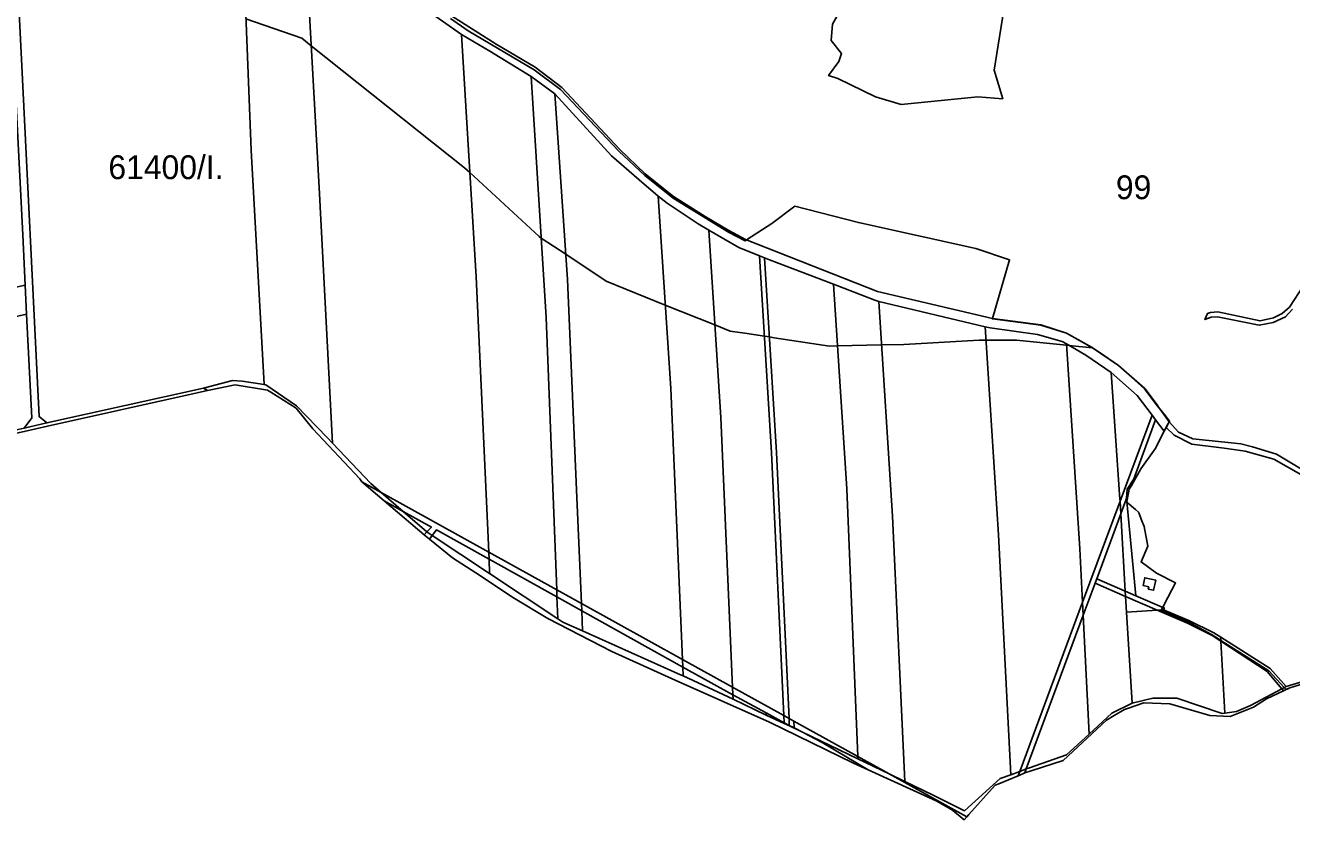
# Model space of a CAD drawing. Extents: x -522079 to -518792, y -1142400 to -1139961.
# Drawn here: x -520002 to -519205, y -1141872 to -1141371 of the extents above; entities that cross this region are included whole.
import ezdxf

# ---------------------------------------------------------------- set-up
doc = ezdxf.new("R2010")
doc.units = 0
for name, color, linetype in [('Hranice parcel', 7, 'Continuous'), ('Parcelní čísla', 7, 'Continuous'), ('Poz předměty', 7, 'Continuous'), ('Značky bodu BP', 7, 'Continuous'), ('Značky budov', 7, 'Continuous')]:
    doc.layers.add(name, color=color, linetype=linetype)

msp = doc.modelspace()

# ---------------------------------------------------------------- linework, layer by layer
at = {"layer": 'Hranice parcel'}
for points in [[(-519998.35, -1141618.37), (-520001.59, -1141552.99), (-520002.49, -1141534.74), (-520004.05, -1141503.1), (-520007.71, -1141429.14), (-520010.91, -1141364.55), (-520011.78, -1141349.43), (-520013.01, -1141327.96), (-520014.41, -1141303.65), (-520015.8, -1141279.3), (-520015.63, -1141269.2), (-520020.82, -1141261.97), (-520005.98, -1141266.96), (-520010.89, -1141271.2), (-520005.29, -1141383.92), (-519993.67, -1141617.6), (-519988.83, -1141621.62), (-520003.08, -1141624.98)], [(-520266.52, -1141683.24), (-520133.69, -1141653.91), (-520003.08, -1141624.98), (-519988.83, -1141621.62), (-519890.16, -1141599.67), (-519887.54, -1141601.15), (-519894.12, -1141602.61), (-519988.36, -1141623.57), (-520003.05, -1141627.05), (-520133.25, -1141655.87), (-520266.08, -1141685.14)], [(-519292.71, -1141616.64), (-519290.49, -1141619.61), (-519305.95, -1141661.39), (-519307.13, -1141663.43), (-519307.53, -1141665.67), (-519312.39, -1141678.8), (-519312.84, -1141670.86)], [(-519215.97, -1141644.42), (-519234.03, -1141639.34), (-519247.24, -1141637.55), (-519267.72, -1141635.03), (-519278.79, -1141629.39), (-519283.88, -1141624.46), (-519281.83, -1141620.82), (-519276.07, -1141627.44), (-519266.93, -1141631.65), (-519236.73, -1141634.83), (-519229.49, -1141636.68), (-519214.22, -1141641.4), (-519195.4, -1141652.58), (-519185.55, -1141666.07), (-519168.83, -1141692.07), (-519157.76, -1141703.36), (-519119.77, -1141724.36), (-519107.07, -1141732.42), (-519111.34, -1141734.71), (-519122.24, -1141726.88), (-519160.32, -1141706.01), (-519170.28, -1141695.6), (-519197.57, -1141654.98)], [(-519790.37, -1141658.77), (-519778.21, -1141665.51), (-519764.48, -1141677.36), (-519776.39, -1141670.73)], [(-519778.21, -1141665.51), (-519710.49, -1141703.04), (-519710.31, -1141707.49), (-519743.43, -1141689.07), (-519746.19, -1141692.62), (-519748.73, -1141690.94), (-519749.42, -1141690.34), (-519746.63, -1141687.29), (-519764.48, -1141677.36)], [(-519312.39, -1141678.8), (-519327.57, -1141719.82), (-519328.61, -1141722.63), (-519336.07, -1141742.78), (-519336.47, -1141734.52), (-519312.84, -1141670.86)], [(-519746.19, -1141692.62), (-519747.91, -1141694.83), (-519751.14, -1141692.22), (-519749.42, -1141690.34), (-519748.73, -1141690.94)], [(-519710.49, -1141703.04), (-519667.71, -1141726.74), (-519667.54, -1141731.28), (-519710.31, -1141707.49)], [(-519309.44, -1141730.94), (-519328.61, -1141722.63), (-519327.57, -1141719.82), (-519309.63, -1141727.6)], [(-519298.29, -1141724.1), (-519297.27, -1141719.22), (-519290.41, -1141720.65), (-519291.74, -1141727), (-519295.11, -1141726.32), (-519294.81, -1141724.84)], [(-519667.54, -1141731.28), (-519667.71, -1141726.74), (-519652.11, -1141735.39), (-519651.91, -1141739.97)], [(-519285.49, -1141739.31), (-519289.52, -1141739.58), (-519309.44, -1141730.94), (-519309.63, -1141727.6), (-519302.86, -1141730.53), (-519284.96, -1141738.29)], [(-519588.39, -1141770.7), (-519588.18, -1141775.42), (-519651.91, -1141739.97), (-519652.11, -1141735.39)], [(-519336.47, -1141734.52), (-519336.07, -1141742.78), (-519371.92, -1141839.65), (-519376.07, -1141841.19)], [(-519192.31, -1141784.44), (-519205.85, -1141788.49), (-519209.88, -1141790.38), (-519211, -1141789.08), (-519208.31, -1141787.64), (-519193.63, -1141783.33), (-519181.21, -1141780.54), (-519173.18, -1141777.23), (-519164.17, -1141772.59), (-519130.56, -1141747.22), (-519111.34, -1141734.71), (-519107.07, -1141732.42), (-519106.29, -1141740.33), (-519117.64, -1141741.85), (-519132.98, -1141750.7), (-519141.38, -1141757.45), (-519162.82, -1141773.79), (-519171.52, -1141778.29), (-519182.83, -1141782.69)], [(-519253.85, -1141753.9), (-519249.47, -1141756.69), (-519249.34, -1141759.14), (-519254.9, -1141755.61), (-519270.39, -1141747.88), (-519289.52, -1141739.58), (-519285.49, -1141739.31), (-519269.54, -1141746.07)], [(-519249.47, -1141756.69), (-519218.36, -1141776.45), (-519208.31, -1141787.64), (-519211, -1141789.08), (-519220.27, -1141778.33), (-519249.34, -1141759.14)], [(-519556.77, -1141792.9), (-519588.18, -1141775.42), (-519588.39, -1141770.7), (-519556.98, -1141788.11)], [(-519556.77, -1141792.9), (-519556.98, -1141788.11), (-519524.56, -1141806.07), (-519524.35, -1141810.51), (-519535.73, -1141804.33)], [(-519524.35, -1141810.51), (-519524.56, -1141806.07), (-519521.37, -1141807.84), (-519521.17, -1141812.18)], [(-519521.17, -1141812.18), (-519521.37, -1141807.84), (-519518.28, -1141809.56), (-519518.08, -1141813.8)], [(-519477.97, -1141833.34), (-519512.87, -1141816.53), (-519518.08, -1141813.8), (-519518.28, -1141809.56), (-519478.03, -1141831.87)], [(-519477.97, -1141833.34), (-519458.26, -1141842.83), (-519409.46, -1141869.87), (-519411.05, -1141871.62), (-519418.41, -1141865.69), (-519428.71, -1141859.77), (-519471.59, -1141840.28), (-519500.53, -1141823.01), (-519512.87, -1141816.53)], [(-519478.03, -1141831.87), (-519458.26, -1141842.83), (-519477.97, -1141833.34)], [(-519377.1, -1141843.96), (-519376.07, -1141841.19), (-519371.92, -1141839.65), (-519372.86, -1141842.19), (-519376.08, -1141843.54)]]:
    msp.add_lwpolyline(points, close=True, dxfattribs=at)
for points in [[(-519733.94, -1141365.09), (-519705.92, -1141383), (-519681.23, -1141397.53), (-519664.49, -1141410.15), (-519628.16, -1141449.15), (-519611.87, -1141464.55), (-519594.12, -1141478.91), (-519574.1, -1141491.51), (-519559.27, -1141500.34), (-519548.85, -1141506.03), (-519465.6, -1141538.79), (-519393.2, -1141555.81), (-519362.75, -1141559.82), (-519346.5, -1141565.05), (-519330.14, -1141574.2), (-519313.9, -1141585.4), (-519297.36, -1141600.15), (-519289.76, -1141610.43), (-519286.19, -1141615.06), (-519281.83, -1141620.82), (-519283.88, -1141624.46), (-519285.15, -1141626.73), (-519290.49, -1141619.61), (-519292.71, -1141616.64), (-519301.98, -1141604.24), (-519318.43, -1141589.84), (-519334.38, -1141578.92), (-519346.66, -1141571.83), (-519349.35, -1141570.28), (-519364.95, -1141565.79), (-519394.67, -1141561.74), (-519397.82, -1141561.07), (-519464.89, -1141545.09), (-519467.42, -1141544.19), (-519493.41, -1141534.2), (-519533.7, -1141518.85), (-519536.79, -1141517.61), (-519539.97, -1141516.35), (-519553.06, -1141511.15), (-519571.87, -1141500.11), (-519578.53, -1141496.09), (-519598.08, -1141483.22), (-519603.81, -1141478.65), (-519615.77, -1141468.45), (-519633.24, -1141453.23), (-519668.96, -1141414.21), (-519683.78, -1141403.39), (-519709.78, -1141387.41), (-519727.64, -1141376.95), (-519751.63, -1141360.04)], [(-519204.3, -1141549.93), (-519208.65, -1141554.69), (-519216.52, -1141558.38), (-519225.22, -1141560.03), (-519251.39, -1141554.86), (-519255.57, -1141555.02), (-519259.41, -1141556.52), (-519257.81, -1141552.73), (-519255.9, -1141551.98), (-519251.3, -1141551.66), (-519224.64, -1141557.32), (-519216.28, -1141555.43), (-519210.78, -1141552.72), (-519206.19, -1141548.7), (-519197.16, -1141534.83)]]:
    msp.add_lwpolyline(points, dxfattribs=at)
at = {"layer": 'Parcelní čísla'}
for points in [[(-519988.83, -1141621.62), (-519993.67, -1141617.6), (-520005.29, -1141383.92), (-520010.89, -1141271.2), (-520005.98, -1141266.96), (-519865.42, -1141315.8), (-519860.18, -1141449.65), (-519851.95, -1141597.5), (-519865.85, -1141595.23), (-519871.86, -1141594.87), (-519890.16, -1141599.67)], [(-519865.42, -1141315.8), (-519825.24, -1141330.38), (-519817.29, -1141473.31), (-519808.88, -1141634.44), (-519812.26, -1141630.88), (-519831.57, -1141610.83), (-519850.96, -1141597.66), (-519851.95, -1141597.5), (-519860.18, -1141449.65)], [(-519825.24, -1141330.38), (-519793.08, -1141341.43), (-519751.63, -1141360.04), (-519727.64, -1141376.95), (-519718.52, -1141529.55), (-519710.49, -1141703.04), (-519778.21, -1141665.51), (-519784.86, -1141659.77), (-519808.88, -1141634.44), (-519817.29, -1141473.31)], [(-519710.49, -1141703.04), (-519718.52, -1141529.55), (-519727.64, -1141376.95), (-519709.78, -1141387.41), (-519683.78, -1141403.39), (-519674.25, -1141555.28), (-519667.71, -1141726.74)], [(-519683.78, -1141403.39), (-519668.96, -1141414.21), (-519660.95, -1141531.22), (-519655.21, -1141663.8), (-519652.11, -1141735.39), (-519667.71, -1141726.74), (-519674.25, -1141555.28)], [(-519660.95, -1141531.22), (-519668.96, -1141414.21), (-519633.24, -1141453.23), (-519615.77, -1141468.45), (-519603.81, -1141478.65), (-519595.83, -1141599.95), (-519588.39, -1141770.7), (-519652.11, -1141735.39), (-519655.21, -1141663.8)], [(-519564.39, -1141618.27), (-519556.98, -1141788.11), (-519588.39, -1141770.7), (-519595.83, -1141599.95), (-519603.81, -1141478.65), (-519598.08, -1141483.22), (-519578.53, -1141496.09), (-519571.87, -1141500.11)], [(-519564.39, -1141618.27), (-519571.87, -1141500.11), (-519553.06, -1141511.15), (-519539.97, -1141516.35), (-519532.32, -1141640.4), (-519524.56, -1141806.07), (-519556.98, -1141788.11)], [(-519539.97, -1141516.35), (-519536.79, -1141517.61), (-519529.23, -1141640.2), (-519521.37, -1141807.84), (-519524.56, -1141806.07), (-519532.32, -1141640.4)], [(-519518.28, -1141809.56), (-519521.37, -1141807.84), (-519529.23, -1141640.2), (-519536.79, -1141517.61), (-519533.7, -1141518.85), (-519493.41, -1141534.2), (-519484.95, -1141663.16), (-519478.03, -1141831.87)], [(-520141.93, -1141565.64), (-520002.49, -1141534.74), (-520001.59, -1141552.99), (-520274.84, -1141614.95), (-520276.82, -1141595.78)], [(-519464.89, -1141545.09), (-519456.22, -1141680.46), (-519448.38, -1141847.58), (-519458.26, -1141842.83), (-519478.03, -1141831.87), (-519484.95, -1141663.16), (-519493.41, -1141534.2), (-519467.42, -1141544.19)], [(-519381.7, -1141843.28), (-519388.28, -1141845.72), (-519410.94, -1141866.01), (-519430.66, -1141856.11), (-519448.38, -1141847.58), (-519456.22, -1141680.46), (-519464.89, -1141545.09), (-519397.82, -1141561.07), (-519389.39, -1141692.08)], [(-520001.59, -1141552.99), (-519998.35, -1141618.37), (-520003.08, -1141624.98), (-520133.69, -1141653.91), (-520266.52, -1141683.24), (-520268.73, -1141674.23), (-520274.84, -1141614.95)], [(-519338.11, -1141700.9), (-519336.47, -1141734.52), (-519376.07, -1141841.19), (-519381.7, -1141843.28), (-519389.39, -1141692.08), (-519397.82, -1141561.07), (-519394.67, -1141561.74), (-519364.95, -1141565.79), (-519349.35, -1141570.28), (-519346.66, -1141571.83)], [(-519312.91, -1141669.62), (-519312.84, -1141670.86), (-519336.47, -1141734.52), (-519338.11, -1141700.9), (-519346.66, -1141571.83), (-519334.38, -1141578.92), (-519318.43, -1141589.84)], [(-519318.43, -1141589.84), (-519301.98, -1141604.24), (-519292.71, -1141616.64), (-519312.84, -1141670.86), (-519312.91, -1141669.62)], [(-519871.86, -1141594.87), (-519865.85, -1141595.23), (-519851.95, -1141597.5), (-519850.96, -1141597.66), (-519831.57, -1141610.83), (-519812.26, -1141630.88), (-519808.88, -1141634.44), (-519784.86, -1141659.77), (-519778.21, -1141665.51), (-519790.37, -1141658.77), (-519791.74, -1141656.89), (-519821.3, -1141625.26), (-519831.88, -1141612.23), (-519847.75, -1141602.33), (-519849.83, -1141601.06), (-519870.13, -1141597.7), (-519887.54, -1141601.15), (-519890.16, -1141599.67)], [(-519776.39, -1141670.73), (-519764.48, -1141677.36), (-519749.42, -1141690.34), (-519751.14, -1141692.22)], [(-519764.48, -1141677.36), (-519746.63, -1141687.29), (-519749.42, -1141690.34)], [(-519710.31, -1141707.49), (-519709.93, -1141716.59), (-519746.19, -1141692.62), (-519743.43, -1141689.07)], [(-519718.63, -1141715.98), (-519733.23, -1141706.57), (-519747.91, -1141694.83), (-519746.19, -1141692.62), (-519709.93, -1141716.59), (-519667.02, -1141744.96), (-519663.82, -1141747.08), (-519651.37, -1141752.53), (-519589.8, -1141780.27), (-519588.09, -1141781.01), (-519556.64, -1141795.77), (-519535.66, -1141805.67), (-519524.32, -1141811.02), (-519521.15, -1141812.55), (-519512.87, -1141816.53), (-519500.53, -1141823.01), (-519471.59, -1141840.28), (-519480.84, -1141836.08), (-519533.59, -1141810.27), (-519593.13, -1141783.65), (-519633.06, -1141765.56), (-519673.22, -1141744.78), (-519694.8, -1141731.79)], [(-519667.54, -1141731.28), (-519667.02, -1141744.96), (-519709.93, -1141716.59), (-519710.31, -1141707.49)], [(-519305.24, -1141798.22), (-519318.06, -1141804.43), (-519332.42, -1141817.72), (-519336.07, -1141742.78), (-519328.61, -1141722.63), (-519309.44, -1141730.94), (-519308.88, -1141740.9)], [(-519667.54, -1141731.28), (-519651.91, -1141739.97), (-519651.37, -1141752.53), (-519663.82, -1141747.08), (-519667.02, -1141744.96)], [(-519289.52, -1141739.58), (-519308.88, -1141740.9), (-519309.44, -1141730.94)], [(-519588.18, -1141775.42), (-519588.09, -1141781.01), (-519589.8, -1141780.27), (-519651.37, -1141752.53), (-519651.91, -1141739.97)], [(-519336.07, -1141742.78), (-519332.42, -1141817.72), (-519346.6, -1141830.84), (-519369.96, -1141838.92), (-519371.92, -1141839.65)], [(-519254.9, -1141755.61), (-519249.34, -1141759.14), (-519246.92, -1141804.45), (-519248.63, -1141804.68), (-519277.03, -1141795.09), (-519292.12, -1141794.98), (-519305.24, -1141798.22), (-519308.88, -1141740.9), (-519289.52, -1141739.58), (-519270.39, -1141747.88)], [(-519220.27, -1141778.33), (-519211, -1141789.08), (-519230.77, -1141799.67), (-519239.54, -1141803.44), (-519246.92, -1141804.45), (-519249.34, -1141759.14)], [(-519556.64, -1141795.77), (-519588.09, -1141781.01), (-519588.18, -1141775.42), (-519556.77, -1141792.9)], [(-519556.64, -1141795.77), (-519556.77, -1141792.9), (-519535.73, -1141804.33), (-519535.66, -1141805.67)], [(-519243.51, -1141806.68), (-519256.37, -1141806.05), (-519281.47, -1141798.57), (-519297.93, -1141798.04), (-519308.25, -1141801.56), (-519310.14, -1141802.21), (-519316.53, -1141805.97), (-519321.4, -1141808.82), (-519348.63, -1141834.32), (-519368.78, -1141840.86), (-519372.86, -1141842.19), (-519371.92, -1141839.65), (-519369.96, -1141838.92), (-519346.6, -1141830.84), (-519332.42, -1141817.72), (-519318.06, -1141804.43), (-519305.24, -1141798.22), (-519292.12, -1141794.98), (-519277.03, -1141795.09), (-519248.63, -1141804.68), (-519246.92, -1141804.45), (-519239.54, -1141803.44), (-519230.77, -1141799.67), (-519211, -1141789.08), (-519209.88, -1141790.38), (-519220.64, -1141795.43), (-519228.74, -1141800.67)], [(-519535.73, -1141804.33), (-519524.35, -1141810.51), (-519524.32, -1141811.02), (-519535.66, -1141805.67)], [(-519521.15, -1141812.55), (-519524.32, -1141811.02), (-519524.35, -1141810.51), (-519521.17, -1141812.18)], [(-519512.87, -1141816.53), (-519521.15, -1141812.55), (-519521.17, -1141812.18), (-519518.08, -1141813.8)], [(-519389.29, -1141849.01), (-519391.5, -1141849.93), (-519408.1, -1141868.36), (-519409.46, -1141869.87), (-519458.26, -1141842.83), (-519448.38, -1141847.58), (-519430.66, -1141856.11), (-519410.94, -1141866.01), (-519388.28, -1141845.72), (-519381.7, -1141843.28), (-519376.07, -1141841.19), (-519377.1, -1141843.96)]]:
    msp.add_lwpolyline(points, close=True, dxfattribs=at)
at = {"layer": 'Poz předměty'}
for points in [[(-519290.49, -1141619.61), (-519285.15, -1141626.73), (-519290.81, -1141638.01), (-519299.72, -1141650.6), (-519305.95, -1141661.39)], [(-519308.5, -1141671.02), (-519302.86, -1141730.53), (-519309.63, -1141727.6), (-519312.39, -1141678.8), (-519307.53, -1141665.67)], [(-519309.63, -1141727.6), (-519327.57, -1141719.82), (-519312.39, -1141678.8)]]:
    msp.add_lwpolyline(points, close=True, dxfattribs=at)
at = {"layer": 'Značky bodu BP'}
for points in [[(-519863.42, -1141366.88), (-519828.32, -1141379.25), (-519822.25, -1141384.07), (-519725.68, -1141460.78), (-519722.45, -1141463.77), (-519678.79, -1141504.16), (-519677.4, -1141505.09), (-519662.03, -1141515.37), (-519636.59, -1141532.38), (-519599.29, -1141547.35), (-519568.09, -1141559.87), (-519558.44, -1141563.74), (-519556.95, -1141563.96), (-519549.16, -1141565.14), (-519536.85, -1141566.99), (-519536.62, -1141567.02), (-519533.71, -1141567.46), (-519530.67, -1141567.92), (-519495.92, -1141573.15), (-519490.86, -1141573.03), (-519463.14, -1141572.42), (-519449.03, -1141572.1), (-519401.62, -1141569.49), (-519397.28, -1141569.49), (-519378.18, -1141569.49), (-519346.61, -1141572.59), (-519345.08, -1141572.74), (-519330.18, -1141574.2), (-519325.31, -1141577.53), (-519313.9, -1141585.33), (-519297.31, -1141600.01), (-519289.56, -1141610.31), (-519288.55, -1141611.63), (-519286.09, -1141614.85), (-519285.08, -1141616.18), (-519281.71, -1141620.6), (-519281.83, -1141620.82), (-519283.73, -1141624.25), (-519283.86, -1141624.48), (-519285, -1141626.52), (-519286.13, -1141628.69), (-519290.81, -1141638.01), (-519299.72, -1141650.6), (-519305.95, -1141661.39), (-519304.41, -1141657.24), (-519308.29, -1141663.27), (-519308.84, -1141669.03), (-519308.86, -1141669.27), (-519307.53, -1141665.67), (-519308.5, -1141671.02), (-519308.44, -1141671.65), (-519303.06, -1141676.16), (-519301.18, -1141677.74), (-519300.85, -1141678.61), (-519299.51, -1141682.18), (-519297.77, -1141686.8), (-519295.29, -1141699.2), (-519299.57, -1141709.24), (-519289.85, -1141716.31), (-519277.9, -1141722.39), (-519285.04, -1141736), (-519286.01, -1141737.83), (-519286.11, -1141738.02), (-519286.86, -1141739.4), (-519287.01, -1141739.67), (-519270.39, -1141746.69), (-519255.22, -1141754.92), (-519250.82, -1141757.69), (-519249.37, -1141758.61), (-519219.1, -1141777.78), (-519209.49, -1141788.27), (-519208.58, -1141789.26), (-519208.35, -1141789.66), (-519209.88, -1141790.38), (-519220.64, -1141795.43), (-519228.74, -1141800.67), (-519243.51, -1141806.68), (-519256.37, -1141806.05), (-519281.47, -1141798.57), (-519297.93, -1141798.04), (-519308.25, -1141801.56), (-519310.14, -1141802.21), (-519316.53, -1141805.97), (-519321.4, -1141808.82), (-519348.63, -1141834.32), (-519368.78, -1141840.86), (-519372.86, -1141842.19), (-519376.08, -1141843.54), (-519377.1, -1141843.96), (-519389.29, -1141849.01), (-519391.5, -1141849.93), (-519408.1, -1141868.36), (-519409.46, -1141869.87), (-519411.05, -1141871.62), (-519418.41, -1141865.69), (-519428.71, -1141859.77), (-519471.59, -1141840.28), (-519480.84, -1141836.08), (-519533.59, -1141810.27), (-519593.13, -1141783.65), (-519633.06, -1141765.56), (-519673.22, -1141744.78), (-519694.8, -1141731.79), (-519718.63, -1141715.98), (-519733.23, -1141706.57), (-519747.91, -1141694.83), (-519751.14, -1141692.22), (-519776.39, -1141670.73), (-519790.37, -1141658.77), (-519791.74, -1141656.89), (-519821.3, -1141625.26), (-519831.88, -1141612.23), (-519847.75, -1141602.33), (-519849.83, -1141601.06), (-519870.13, -1141597.7), (-519887.54, -1141601.15), (-519894.12, -1141602.61), (-519988.36, -1141623.57), (-520003.05, -1141627.05)], [(-519734.68, -1141366.82), (-519723.37, -1141374.45), (-519681.85, -1141399.04), (-519665.4, -1141411.5), (-519628.6, -1141450.42), (-519612.25, -1141465.74), (-519594.44, -1141480.03), (-519559.52, -1141501.31), (-519549.08, -1141506.95), (-519548.11, -1141506.32), (-519532.23, -1141495.98), (-519517.64, -1141485.04), (-519477.67, -1141495.35), (-519403.69, -1141511.76), (-519382.45, -1141518.76), (-519393.21, -1141555.81), (-519393.29, -1141556.08), (-519362.83, -1141559.96), (-519346.58, -1141565.12), (-519330.41, -1141574.07), (-519330.18, -1141574.2), (-519345.08, -1141572.74), (-519346.61, -1141572.59), (-519378.18, -1141569.49), (-519397.28, -1141569.49), (-519401.62, -1141569.49), (-519449.03, -1141572.1), (-519463.14, -1141572.42), (-519490.86, -1141573.03), (-519495.92, -1141573.15), (-519530.67, -1141567.92), (-519533.71, -1141567.46), (-519536.62, -1141567.02), (-519536.85, -1141566.99), (-519549.16, -1141565.14), (-519556.95, -1141563.96), (-519558.44, -1141563.74), (-519568.09, -1141559.87), (-519599.29, -1141547.35), (-519636.59, -1141532.38), (-519662.03, -1141515.37), (-519677.4, -1141505.09), (-519678.79, -1141504.16), (-519722.45, -1141463.77), (-519725.68, -1141460.78), (-519822.25, -1141384.07), (-519828.32, -1141379.25), (-519863.42, -1141366.88)], [(-519192.31, -1141784.44), (-519205.85, -1141788.49), (-519208.35, -1141789.66), (-519208.58, -1141789.26), (-519209.49, -1141788.27), (-519219.1, -1141777.78), (-519249.37, -1141758.61), (-519250.82, -1141757.69), (-519255.22, -1141754.92), (-519270.39, -1141746.69), (-519287.01, -1141739.67), (-519286.86, -1141739.4), (-519286.11, -1141738.02), (-519286.01, -1141737.83), (-519285.04, -1141736), (-519277.9, -1141722.39), (-519289.85, -1141716.31), (-519299.57, -1141709.24), (-519295.29, -1141699.2), (-519297.77, -1141686.8), (-519299.51, -1141682.18), (-519300.85, -1141678.61), (-519301.18, -1141677.74), (-519303.06, -1141676.16), (-519308.44, -1141671.65), (-519308.5, -1141671.02), (-519307.53, -1141665.67), (-519308.86, -1141669.27), (-519308.84, -1141669.03), (-519308.29, -1141663.27), (-519304.41, -1141657.24), (-519305.95, -1141661.39), (-519299.72, -1141650.6), (-519290.81, -1141638.01), (-519286.13, -1141628.69), (-519285, -1141626.52), (-519283.86, -1141624.48), (-519283.73, -1141624.25), (-519281.83, -1141620.82), (-519281.71, -1141620.6), (-519285.08, -1141616.18), (-519286.09, -1141614.85), (-519288.55, -1141611.63), (-519289.56, -1141610.31), (-519297.31, -1141600.01), (-519313.9, -1141585.33), (-519325.31, -1141577.53), (-519330.18, -1141574.2), (-519330.41, -1141574.07), (-519346.58, -1141565.12), (-519362.83, -1141559.96), (-519393.29, -1141556.08), (-519393.21, -1141555.81), (-519382.45, -1141518.76), (-519403.69, -1141511.76), (-519477.67, -1141495.35), (-519517.64, -1141485.04), (-519532.23, -1141495.98), (-519548.11, -1141506.32), (-519549.08, -1141506.95), (-519559.52, -1141501.31), (-519594.44, -1141480.03), (-519612.25, -1141465.74), (-519628.6, -1141450.42), (-519665.4, -1141411.5), (-519681.85, -1141399.04), (-519723.37, -1141374.45), (-519734.68, -1141366.82)]]:
    msp.add_lwpolyline(points, dxfattribs=at)
at = {"layer": 'Značky budov'}
for points in [[(-519494.92, -1141380.6), (-519493.9, -1141370.24), (-519484.66, -1141353.81), (-519477.91, -1141348.96), (-519470.8, -1141337.38), (-519465.42, -1141322.27), (-519385.2, -1141356.16), (-519392.16, -1141399.31), (-519386.73, -1141417.35), (-519402.53, -1141416.1), (-519450.75, -1141420.94), (-519466.91, -1141416.21), (-519490.7, -1141404.57), (-519496.45, -1141402.69), (-519489.99, -1141393.96), (-519488.36, -1141388.76)], [(-519297.27, -1141719.22), (-519298.29, -1141724.1), (-519294.81, -1141724.84), (-519295.11, -1141726.32), (-519291.74, -1141727), (-519290.41, -1141720.65)]]:
    msp.add_lwpolyline(points, close=True, dxfattribs=at)
for points in [[(-519493.9, -1141370.24), (-519494.92, -1141380.6), (-519488.36, -1141388.76), (-519489.99, -1141393.96), (-519496.45, -1141402.69), (-519490.7, -1141404.57), (-519466.91, -1141416.21), (-519450.75, -1141420.94), (-519402.53, -1141416.1), (-519386.73, -1141417.35), (-519392.16, -1141399.31), (-519385.2, -1141356.16)], [(-519195.4, -1141652.58), (-519214.22, -1141641.4), (-519229.49, -1141636.68), (-519236.73, -1141634.83), (-519266.93, -1141631.65), (-519276.07, -1141627.44), (-519281.83, -1141620.82), (-519286.19, -1141615.06), (-519289.76, -1141610.43), (-519297.36, -1141600.15), (-519313.9, -1141585.4), (-519330.14, -1141574.2), (-519346.5, -1141565.05), (-519362.75, -1141559.82), (-519393.2, -1141555.81), (-519465.6, -1141538.79), (-519548.85, -1141506.03), (-519559.27, -1141500.34), (-519574.1, -1141491.51), (-519594.12, -1141478.91), (-519611.87, -1141464.55), (-519628.16, -1141449.15), (-519664.49, -1141410.15), (-519681.23, -1141397.53), (-519705.92, -1141383), (-519733.94, -1141365.09)], [(-519197.16, -1141534.83), (-519206.19, -1141548.7), (-519210.78, -1141552.72), (-519216.28, -1141555.43), (-519224.64, -1141557.32), (-519251.3, -1141551.66), (-519255.9, -1141551.98), (-519257.81, -1141552.73), (-519259.41, -1141556.52), (-519255.57, -1141555.02), (-519251.39, -1141554.86), (-519225.22, -1141560.03), (-519216.52, -1141558.38), (-519208.65, -1141554.69), (-519204.3, -1141549.93)], [(-519193.63, -1141783.33), (-519208.31, -1141787.64), (-519218.36, -1141776.45), (-519249.47, -1141756.69), (-519253.85, -1141753.9), (-519269.54, -1141746.07), (-519285.49, -1141739.31), (-519284.96, -1141738.29), (-519302.86, -1141730.53), (-519308.5, -1141671.02), (-519307.53, -1141665.67), (-519307.13, -1141663.43), (-519305.95, -1141661.39), (-519299.72, -1141650.6), (-519290.81, -1141638.01), (-519285.15, -1141626.73), (-519283.88, -1141624.46), (-519278.79, -1141629.39), (-519267.72, -1141635.03), (-519247.24, -1141637.55), (-519234.03, -1141639.34), (-519215.97, -1141644.42), (-519197.57, -1141654.98)]]:
    msp.add_lwpolyline(points, dxfattribs=at)

# ---------------------------------------------------------------- texts
at = {"layer": 'Značky bodu BP'}
for s, rotation, p in [('61400/I.', 360, (-519950.07, -1141467.98)), ('99', 0, (-519315.48, -1141480.63))]:
    msp.add_text(s, height=15, rotation=rotation, dxfattribs=at).set_placement(p)

doc.saveas('drawing.dxf')
